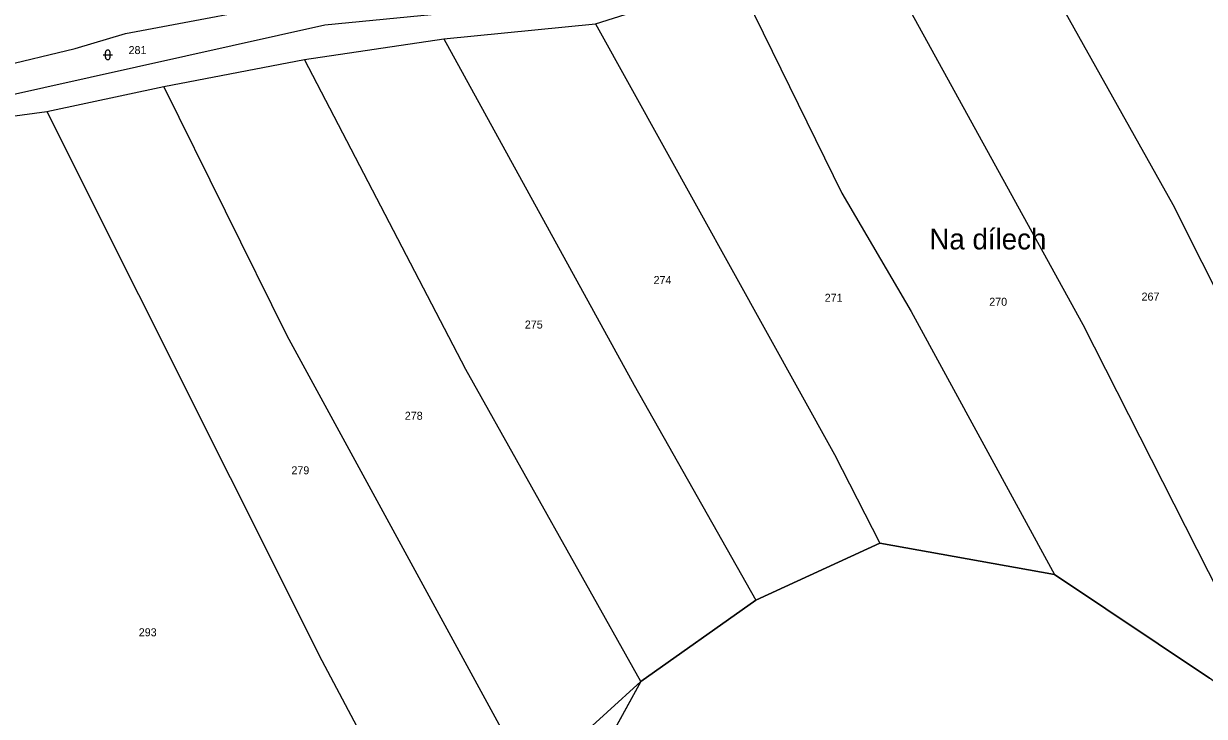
# Model space of a CAD drawing. Extents: x -760642 to -757221, y -1092371 to -1088855.
# Drawn here: x -759004.6 to -758753.7, y -1089533.4 to -1089386.3 of the extents above; entities that cross this region are included whole.
import ezdxf

# ---------------------------------------------------------------- set-up
doc = ezdxf.new("R2010")
doc.units = 0
for name, color, linetype in [('Vrstva 1', 7, 'Continuous'), ('Vrstva 15', 7, 'Continuous'), ('Vrstva 18', 7, 'Continuous'), ('Vrstva 25', 7, 'Continuous'), ('Vrstva 26', 7, 'Continuous'), ('Vrstva 27', 7, 'Continuous')]:
    doc.layers.add(name, color=color, linetype=linetype)

msp = doc.modelspace()

# ---------------------------------------------------------------- linework, layer by layer
at = {"layer": 'Vrstva 1'}
for p, q in [((-758823.94, -1089369.43), (-758779.56, -1089450.18)), ((-758883.06, -1089386.31), (-758853.05, -1089376.83)), ((-758853.05, -1089376.83), (-758830.77, -1089422.32)), ((-758785.74, -1089379.46), (-758760.41, -1089424.72)), ((-758982.96, -1089388.36), (-758942.91, -1089380.82)), ((-758940.61, -1089386.57), (-758891.8, -1089381.78)), ((-759029.85, -1089406.38), (-758940.61, -1089386.57)), ((-758915.3, -1089389.54), (-758883.06, -1089386.31)), ((-758883.06, -1089386.31), (-758832.33, -1089477.78)), ((-758993.67, -1089391.57), (-758982.96, -1089388.36)), ((-758944.92, -1089393.9), (-758915.3, -1089389.54)), ((-758915.3, -1089389.54), (-758874.88, -1089463.05)), ((-759031.69, -1089400.74), (-758993.67, -1089391.57)), ((-758974.82, -1089399.65), (-758944.92, -1089393.9)), ((-758910.63, -1089459.76), (-758944.92, -1089393.9)), ((-758999.66, -1089404.98), (-758974.82, -1089399.65)), ((-758948.57, -1089452.61), (-758974.82, -1089399.65)), ((-759028.28, -1089408.84), (-758999.66, -1089404.98)), ((-758999.66, -1089404.98), (-758941.26, -1089521.5)), ((-758830.77, -1089422.32), (-758816.02, -1089447.41)), ((-758760.41, -1089424.72), (-758713.71, -1089517.56)), ((-758816.02, -1089447.41), (-758785.52, -1089503.26)), ((-758779.56, -1089450.18), (-758742.45, -1089523.27)), ((-758896.88, -1089547.28), (-758948.57, -1089452.61)), ((-758873.48, -1089525.96), (-758910.63, -1089459.76)), ((-758874.88, -1089463.05), (-758849.04, -1089508.7)), ((-758832.33, -1089477.78), (-758822.68, -1089496.65)), ((-758849.04, -1089508.7), (-758822.68, -1089496.65)), ((-758822.68, -1089496.65), (-758785.52, -1089503.26)), ((-758785.52, -1089503.26), (-758752.59, -1089525.27)), ((-758873.48, -1089525.96), (-758849.04, -1089508.7)), ((-758941.26, -1089521.5), (-758903.65, -1089591.92)), ((-758896.88, -1089547.28), (-758873.48, -1089525.96)), ((-758873.48, -1089525.96), (-758890.87, -1089557.65))]:
    msp.add_line(p, q, dxfattribs=at)
at = {"layer": 'Vrstva 25'}
for p, q in [((-758987.21, -1089393.42), (-758987.21, -1089392.42)), ((-758986.21, -1089393.42), (-758986.21, -1089392.42)), ((-758987.71, -1089392.92), (-758985.71, -1089392.92))]:
    msp.add_line(p, q, dxfattribs=at)
for centre, start, end in [((-758986.71, -1089392.42), 0, 180), ((-758986.71, -1089393.42), 180, 0)]:
    msp.add_arc(centre, 0.5, start, end, dxfattribs=at)
at = {"layer": 'Vrstva 26'}
msp.add_lwpolyline([(-758778.318, -1089587.268), (-758749.97, -1089575.49), (-758734.24, -1089564.01), (-758723.83, -1089546.57), (-758746.01, -1089530.03), (-758752.59, -1089525.27), (-758785.52, -1089503.26), (-758822.68, -1089496.65), (-758849.04, -1089508.7), (-758873.48, -1089525.96), (-758890.87, -1089557.65), (-758886.37, -1089574.72), (-758883.785, -1089563.797)], dxfattribs=at)
at = {"layer": 'Vrstva 27'}
msp.add_lwpolyline([(-758752.59, -1089525.27), (-758785.52, -1089503.26), (-758822.68, -1089496.65), (-758849.04, -1089508.7), (-758873.48, -1089525.96), (-758890.87, -1089557.65), (-758886.37, -1089574.72), (-758911.24, -1089618.71), (-758932.33, -1089605.15), (-758934.28, -1089610.09), (-758964.56, -1089686.74)], dxfattribs=at)

# ---------------------------------------------------------------- texts
at = {"layer": 'Vrstva 15'}
msp.add_text('Na dílech', height=4.4, dxfattribs=at).set_placement((-758812.14, -1089434.24))
at = {"layer": 'Vrstva 18'}
for s, p in [('281', (-758982.296, -1089392.76)), ('274', (-758870.74, -1089441.59)), ('271', (-758834.38, -1089445.36)), ('270', (-758799.41, -1089446.2)), ('267', (-758767.05, -1089445.11)), ('275', (-758898.09, -1089451.04)), ('278', (-758923.6, -1089470.41)), ('279', (-758947.69, -1089481.99)), ('293', (-758980.13, -1089516.39))]:
    msp.add_text(s, height=1.7, dxfattribs=at).set_placement(p)

doc.saveas('drawing.dxf')
